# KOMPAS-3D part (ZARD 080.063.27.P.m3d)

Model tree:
1. Булева операция:1
2. Булева операция:2
3. Булева операция:3
4. Булева операция:4
5. Булева операция:5
6. Булева операция:6
7. Булева операция:7
8. Булева операция:8
9. Булева операция:9
10. Булева операция:10
11. Булева операция:11
12. Булева операция:12
13. Булева операция:13
14. Булева операция:14
15. Булева операция:15
16. Булева операция:16
17. Булева операция:17
18. Булева операция:18
19. Булева операция:19
20. Булева операция:20
21. Булева операция:21
22. Булева операция:22
23. Булева операция:23
24. Булева операция:24

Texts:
  ЗАРД 080.063.27-ХХ.Р
  Кран шаровой фланцевый
  ООО "ИК Энерпред-Ярдос"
